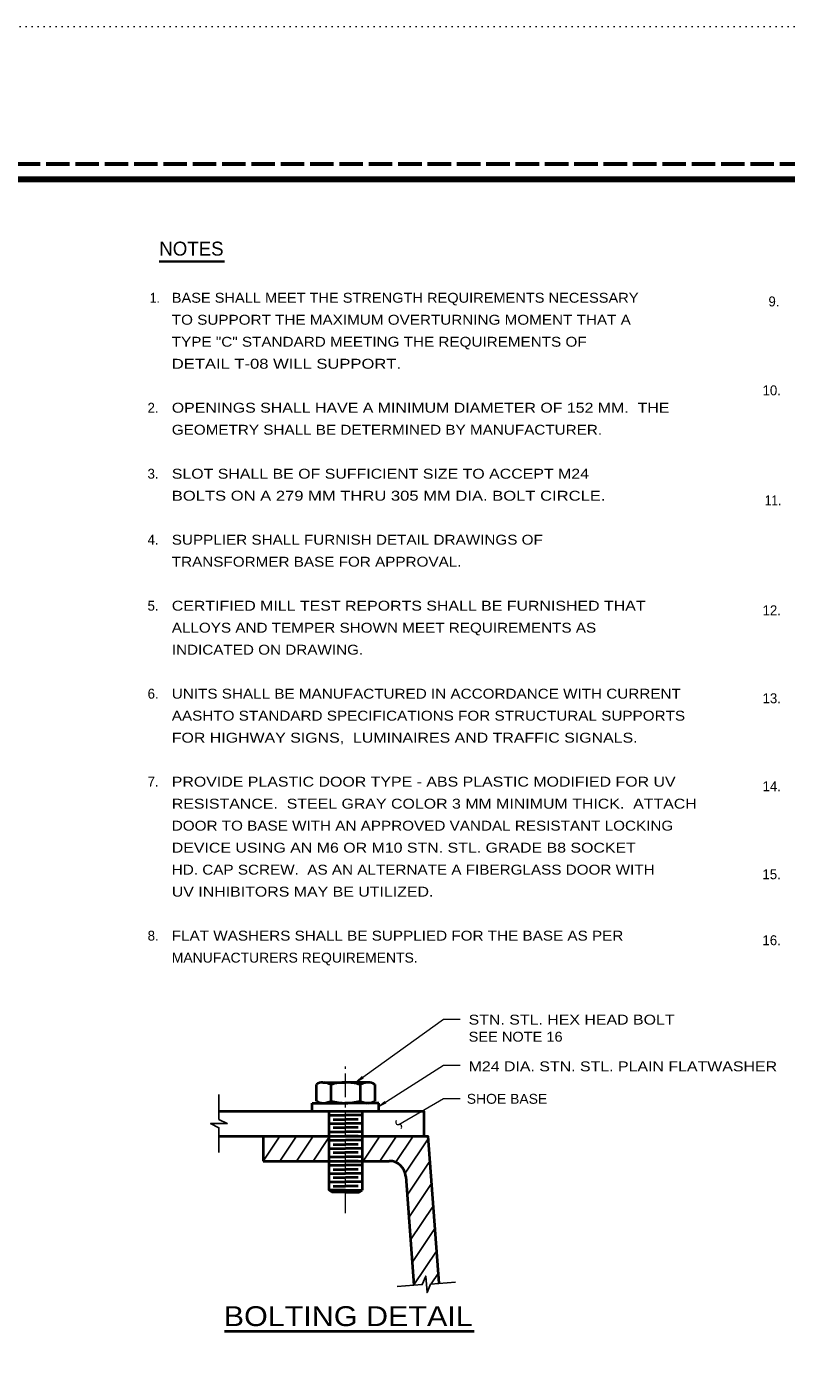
# Model space of a CAD drawing. Extents: x 312583 to 312854, y 144419 to 144597.
# Drawn here: x 312751.7 to 312810, y 144495.2 to 144596.8 of the extents above; entities that cross this region are included whole.
import ezdxf
from ezdxf.enums import TextEntityAlignment as Align

# ---------------------------------------------------------------- set-up
doc = ezdxf.new("R2010")
doc.units = 0
doc.header["$LTSCALE"] = 0.3
for name, pattern in [('DOTTED', [1.5, 0.3, -1.2]), ('LONG_DASH_SHORT_DASH', [9.9, 6, -1.2, 1.5, -1.2]), ('LONG_DASHED', [7.5, 6, -1.5])]:
    doc.linetypes.add(name, pattern=pattern)
for name, color, linetype, lineweight in [('1', 7, 'Continuous', 40), ('2', 7, 'Continuous', 13), ('62', 7, 'DOTTED', 13), ('63', 7, 'LONG_DASHED', 60)]:
    doc.layers.add(name, color=color, linetype=linetype, lineweight=lineweight)

msp = doc.modelspace()

# ---------------------------------------------------------------- linework, layer by layer
at = {"layer": '1', "linetype": 'LONG_DASH_SHORT_DASH', "lineweight": 13}
msp.add_line((312776.1598, 144505.7853), (312776.1598, 144517.0323), dxfattribs=at)
at = {"layer": '1'}
for p, q in [((312773.9211, 144515.66), (312773.9211, 144514.3873)), ((312774.4118, 144515.821), (312776.1598, 144515.821)), ((312775.0405, 144515.66), (312775.0405, 144514.3873)), ((312777.9078, 144515.821), (312776.1598, 144515.821)), ((312777.2791, 144515.66), (312777.2791, 144514.3873)), ((312778.3985, 144515.66), (312778.3985, 144514.3873)), ((312773.5991, 144513.6207), (312773.5991, 144514.2263)), ((312773.5991, 144514.2263), (312776.1598, 144514.2263)), ((312774.8795, 144513.6207), (312774.8795, 144507.5563)), ((312774.8795, 144513.3063), (312776.1598, 144513.3063)), ((312778.7128, 144514.2263), (312776.1598, 144514.2263)), ((312777.4401, 144513.3063), (312776.1598, 144513.3063)), ((312777.4401, 144513.6207), (312777.4401, 144507.5563)), ((312778.7128, 144513.6207), (312778.7128, 144514.2263)), ((312774.8795, 144512.6623), (312776.1598, 144512.6623)), ((312775.2015, 144512.9843), (312776.1598, 144512.9843)), ((312775.2015, 144512.348), (312776.1598, 144512.348)), ((312777.1181, 144512.9843), (312776.1598, 144512.9843)), ((312777.4401, 144512.6623), (312776.1598, 144512.6623)), ((312777.1181, 144512.348), (312776.1598, 144512.348)), ((312774.8795, 144512.026), (312776.1598, 144512.026)), ((312774.8795, 144511.3897), (312776.1598, 144511.3897)), ((312775.2015, 144511.704), (312776.1598, 144511.704)), ((312777.4401, 144512.026), (312776.1598, 144512.026)), ((312777.1181, 144511.704), (312776.1598, 144511.704)), ((312777.4401, 144511.3897), (312776.1598, 144511.3897)), ((312774.8795, 144510.7457), (312776.1598, 144510.7457)), ((312775.2015, 144511.0677), (312776.1598, 144511.0677)), ((312775.2015, 144510.4313), (312776.1598, 144510.4313)), ((312777.1181, 144511.0677), (312776.1598, 144511.0677)), ((312777.4401, 144510.7457), (312776.1598, 144510.7457)), ((312777.1181, 144510.4313), (312776.1598, 144510.4313)), ((312774.8795, 144510.1093), (312776.1598, 144510.1093)), ((312774.8795, 144509.473), (312776.1598, 144509.473)), ((312775.2015, 144509.7873), (312776.1598, 144509.7873)), ((312777.4401, 144510.1093), (312776.1598, 144510.1093)), ((312777.1181, 144509.7873), (312776.1598, 144509.7873)), ((312777.4401, 144509.473), (312776.1598, 144509.473)), ((312774.8795, 144508.829), (312776.1598, 144508.829)), ((312775.2015, 144509.151), (312776.1598, 144509.151)), ((312775.2015, 144508.5147), (312776.1598, 144508.5147)), ((312777.1181, 144509.151), (312776.1598, 144509.151)), ((312777.4401, 144508.829), (312776.1598, 144508.829)), ((312777.1181, 144508.5147), (312776.1598, 144508.5147)), ((312774.8795, 144508.1927), (312776.1598, 144508.1927)), ((312776.1598, 144507.5563), (312774.8795, 144507.5563)), ((312775.1095, 144507.3953), (312774.8795, 144507.5563)), ((312776.1598, 144507.3953), (312775.1095, 144507.3953)), ((312775.2015, 144507.8707), (312776.1598, 144507.8707)), ((312777.4401, 144508.1927), (312776.1598, 144508.1927)), ((312777.1181, 144507.8707), (312776.1598, 144507.8707)), ((312776.1598, 144507.5563), (312777.4401, 144507.5563)), ((312776.1598, 144507.3953), (312777.2101, 144507.3953)), ((312777.2101, 144507.3953), (312777.4401, 144507.5563))]:
    msp.add_line(p, q, dxfattribs=at)
at = {"layer": '1', "lineweight": 158}
msp.add_lwpolyline([(312616.5, 144423.1446), (312616.5, 144585.0846), (312849, 144585.0846)], dxfattribs=at)
at = {"layer": '1'}
for centre, radius, start, end in [((312774.4411, 144514.8966), 0.9222, 91.66257, 124.1297), ((312773.9958, 144513.2358), 2.6408, 66.63635, 78.22986), ((312776.2767, 144511.0567), 4.7658, 91.405, 105.00202), ((312776.0429, 144511.0567), 4.7658, 74.99798, 88.595), ((312778.3238, 144513.2358), 2.6408, 101.77014, 113.36365), ((312777.8785, 144514.8966), 0.9222, 55.8703, 88.33743), ((312774.4411, 144515.1507), 0.9222, 235.8703, 268.33743), ((312773.9958, 144516.8116), 2.6408, 281.77014, 293.36365), ((312776.2767, 144518.9907), 4.7658, 254.99798, 268.595), ((312776.0429, 144518.9907), 4.7658, 271.405, 285.00202), ((312778.3238, 144516.8116), 2.6408, 246.63635, 258.22986), ((312777.8785, 144515.1507), 0.9222, 271.66257, 304.1297)]:
    msp.add_arc(centre, radius, start, end, dxfattribs=at)
at = {"layer": '2', "lineweight": 35}
msp.add_line((312761.8685, 144578.7549), (312766.8887, 144578.7549), dxfattribs=at)
at = {"layer": '2'}
for p, q in [((312777.0185, 144515.8823), (312783.6808, 144520.6587)), ((312783.6808, 144520.6587), (312784.9611, 144520.6587)), ((312778.7281, 144513.9963), (312783.6808, 144517.1473)), ((312783.6808, 144517.1473), (312784.9611, 144517.1473)), ((312777.0185, 144515.8823), (312777.4401, 144516.281)), ((312777.0185, 144515.8823), (312777.5245, 144516.166)), ((312777.4401, 144516.281), (312777.3328, 144516.1123)), ((312777.5245, 144516.166), (312777.3328, 144516.1123)), ((312778.7281, 144513.9963), (312779.1805, 144514.3643)), ((312779.1805, 144514.3643), (312779.0655, 144514.2033)), ((312780.2385, 144512.5857), (312783.6808, 144514.5867)), ((312783.6808, 144514.5867), (312784.9611, 144514.5867)), ((312778.7281, 144513.9963), (312779.2571, 144514.2417)), ((312779.2571, 144514.2417), (312779.0655, 144514.2033))]:
    msp.add_line(p, q, dxfattribs=at)
at = {"layer": '2', "lineweight": 40}
for p, q in [((312769.8501, 144511.704), (312769.8501, 144509.7873)), ((312769.8501, 144509.7873), (312779.5101, 144509.7873)), ((312780.7828, 144508.6067), (312781.4038, 144500.2653)), ((312766.8842, 144496.7465), (312786.0115, 144496.7465))]:
    msp.add_line(p, q, dxfattribs=at)
at = {"layer": '2', "lineweight": 25}
for p, q in [((312771.1228, 144511.704), (312769.8501, 144509.7873)), ((312772.4031, 144511.704), (312771.1228, 144509.7873)), ((312773.6835, 144511.704), (312772.4031, 144509.7873)), ((312774.8795, 144511.589), (312773.6835, 144509.7873)), ((312778.7895, 144511.704), (312777.5091, 144509.7873)), ((312780.0698, 144511.704), (312778.7895, 144509.7873)), ((312781.3501, 144511.704), (312780.0008, 144509.6877)), ((312782.4848, 144511.497), (312780.7368, 144508.8673)), ((312782.6151, 144509.7797), (312780.8901, 144507.1807)), ((312782.7455, 144508.0547), (312781.0128, 144505.4633)), ((312782.8758, 144506.3297), (312781.1431, 144503.7383)), ((312783.0061, 144504.6047), (312781.2735, 144502.0133)), ((312783.1288, 144502.8797), (312781.4038, 144500.2883)), ((312783.2591, 144501.1547), (312782.7301, 144500.365))]:
    msp.add_line(p, q, dxfattribs=at)
for points in [[(312766.4538, 144510.4313), (312766.4538, 144512.3403), (312765.8175, 144512.6623), (312767.0901, 144512.6623), (312766.4538, 144512.9843), (312766.4538, 144514.901)], [(312780.1311, 144500.1733), (312782.0401, 144500.3113), (312782.3085, 144500.9707), (312782.4081, 144499.698), (312782.6765, 144500.3573), (312784.5855, 144500.503)]]:
    msp.add_lwpolyline(points, dxfattribs=at)
at = {"layer": '2', "lineweight": 40}
for points in [[(312766.4538, 144513.6207), (312782.1551, 144513.6207), (312782.1551, 144511.704)], [(312766.4538, 144511.704), (312782.4695, 144511.704), (312783.3128, 144500.411)]]:
    msp.add_lwpolyline(points, dxfattribs=at)
at = {"layer": '2'}
for centre, start, end in [((312780.1904, 144512.7617), 136.06269, 286.06269), ((312780.2898, 144512.4165), 316.06269, 106.06269)]:
    msp.add_arc(centre, 0.1796, start, end, dxfattribs=at)
at = {"layer": '2', "lineweight": 40}
msp.add_arc((312779.5069, 144508.5121), 1.2778, 4.26806, 90, dxfattribs=at)
at = {"layer": '62'}
msp.add_line((312601.2, 144596.7846), (312853.5, 144596.7846), dxfattribs=at)
at = {"layer": '63'}
msp.add_line((312851.75, 144586.2246), (312583.526, 144586.2246), dxfattribs=at)

# ---------------------------------------------------------------- texts
at = {"layer": '2'}
msp.add_text('NOTES', height=1.07, dxfattribs=at).set_placement((312764.3486, 144579.217), align=Align.CENTER)
for s, width, p in [('1.', 0.9, (312761.1587, 144575.6029)), ('BASE SHALL MEET THE STRENGTH REQUIREMENTS NECESSARY ', 1.1, (312762.8422, 144575.6029)), ('TO SUPPORT THE MAXIMUM OVERTURNING MOMENT THAT A  ', 1.15, (312762.8422, 144573.9163)), ('TYPE "C" STANDARD MEETING THE REQUIREMENTS OF  ', 1.15, (312762.8422, 144572.2296)), ('DETAIL T-08 WILL SUPPORT. ', 1.25, (312762.8422, 144570.5429)), ('OPENINGS SHALL HAVE A MINIMUM DIAMETER OF 152 MM.  THE  ', 1.2, (312762.8422, 144567.1696)), ('GEOMETRY SHALL BE DETERMINED BY MANUFACTURER.    ', 1.15, (312762.8422, 144565.4829)), ('SLOT SHALL BE OF SUFFICIENT SIZE TO ACCEPT M24', 1.2, (312762.8422, 144562.1096)), ('BOLTS ON A 279 MM THRU 305 MM DIA. BOLT CIRCLE. ', 1.25, (312762.8422, 144560.4229)), ('11.', 0.9, (312808.3042, 144560.072)), ('SUPPLIER SHALL FURNISH DETAIL DRAWINGS OF  ', 1.15, (312762.8422, 144557.0496)), ('TRANSFORMER BASE FOR APPROVAL.  ', 1.15, (312762.8422, 144555.3629)), ('CERTIFIED MILL TEST REPORTS SHALL BE FURNISHED THAT   ', 1.2, (312762.8422, 144551.9896)), ('ALLOYS AND TEMPER SHOWN MEET REQUIREMENTS AS    ', 1.15, (312762.8422, 144550.3029)), ('INDICATED ON DRAWING.  ', 1.15, (312762.8422, 144548.6163)), ('UNITS SHALL BE MANUFACTURED IN ACCORDANCE WITH CURRENT  ', 1.15, (312762.8422, 144545.2429)), ('AASHTO STANDARD SPECIFICATIONS FOR STRUCTURAL SUPPORTS  ', 1.15, (312762.8422, 144543.5563)), ('FOR HIGHWAY SIGNS,  LUMINAIRES AND TRAFFIC SIGNALS.  ', 1.2, (312762.8422, 144541.8696)), ('PROVIDE PLASTIC DOOR TYPE - ABS PLASTIC MODIFIED FOR UV', 1.2, (312762.8422, 144538.4963)), ('RESISTANCE.  STEEL GRAY COLOR 3 MM MINIMUM THICK.  ATTACH', 1.2, (312762.8422, 144536.8096)), ('DOOR TO BASE WITH AN APPROVED VANDAL RESISTANT LOCKING', 1.15, (312762.8422, 144535.1229)), ('DEVICE USING AN M6 OR M10 STN. STL. GRADE B8 SOCKET', 1.2, (312762.8422, 144533.4363)), ('HD. CAP SCREW.  AS AN ALTERNATE A FIBERGLASS DOOR WITH', 1.15, (312762.8422, 144531.7496)), ('UV INHIBITORS MAY BE UTILIZED.', 1.2, (312762.8422, 144530.0629)), ('FLAT WASHERS SHALL BE SUPPLIED FOR THE BASE AS PER', 1.15, (312762.8422, 144526.6896)), ('MANUFACTURERS REQUIREMENTS.', 1.05, (312762.8422, 144525.0029)), ('STN. STL. HEX HEAD BOLT', 1.2, (312785.5975, 144520.2495)), ('SEE NOTE 16', 1.1, (312785.5975, 144518.9403)), ('M24 DIA. STN. STL. PLAIN FLATWASHER', 1.2, (312785.5975, 144516.6679)), ('SHOE BASE', 1.05, (312785.4573, 144514.1775))]:
    msp.add_text(s, height=0.76, dxfattribs=dict(at, width=width)).set_placement(p)
for s, p in [('9.', (312808.5845, 144575.3222)), ('10.', (312808.1316, 144568.5054)), ('2.', (312760.9837, 144567.1696)), ('3.', (312760.9837, 144562.1096)), ('4.', (312760.9837, 144557.0496)), ('5.', (312760.9837, 144551.9896)), ('12.', (312808.1307, 144551.6387)), ('6.', (312760.9871, 144545.2429)), ('13.', (312808.1307, 144544.892)), ('7.', (312760.9837, 144538.4963)), ('14.', (312808.1307, 144538.1454)), ('15.', (312808.1231, 144531.3987)), ('8.', (312760.9913, 144526.6896)), ('16.', (312808.1235, 144526.3387))]:
    msp.add_text(s, height=0.76, dxfattribs=at).set_placement(p)
at = {"layer": '2', "width": 1.15}
msp.add_text('BOLTING DETAIL', height=1.52, dxfattribs=at).set_placement((312776.3698, 144497.133), align=Align.CENTER)

doc.saveas('drawing.dxf')
